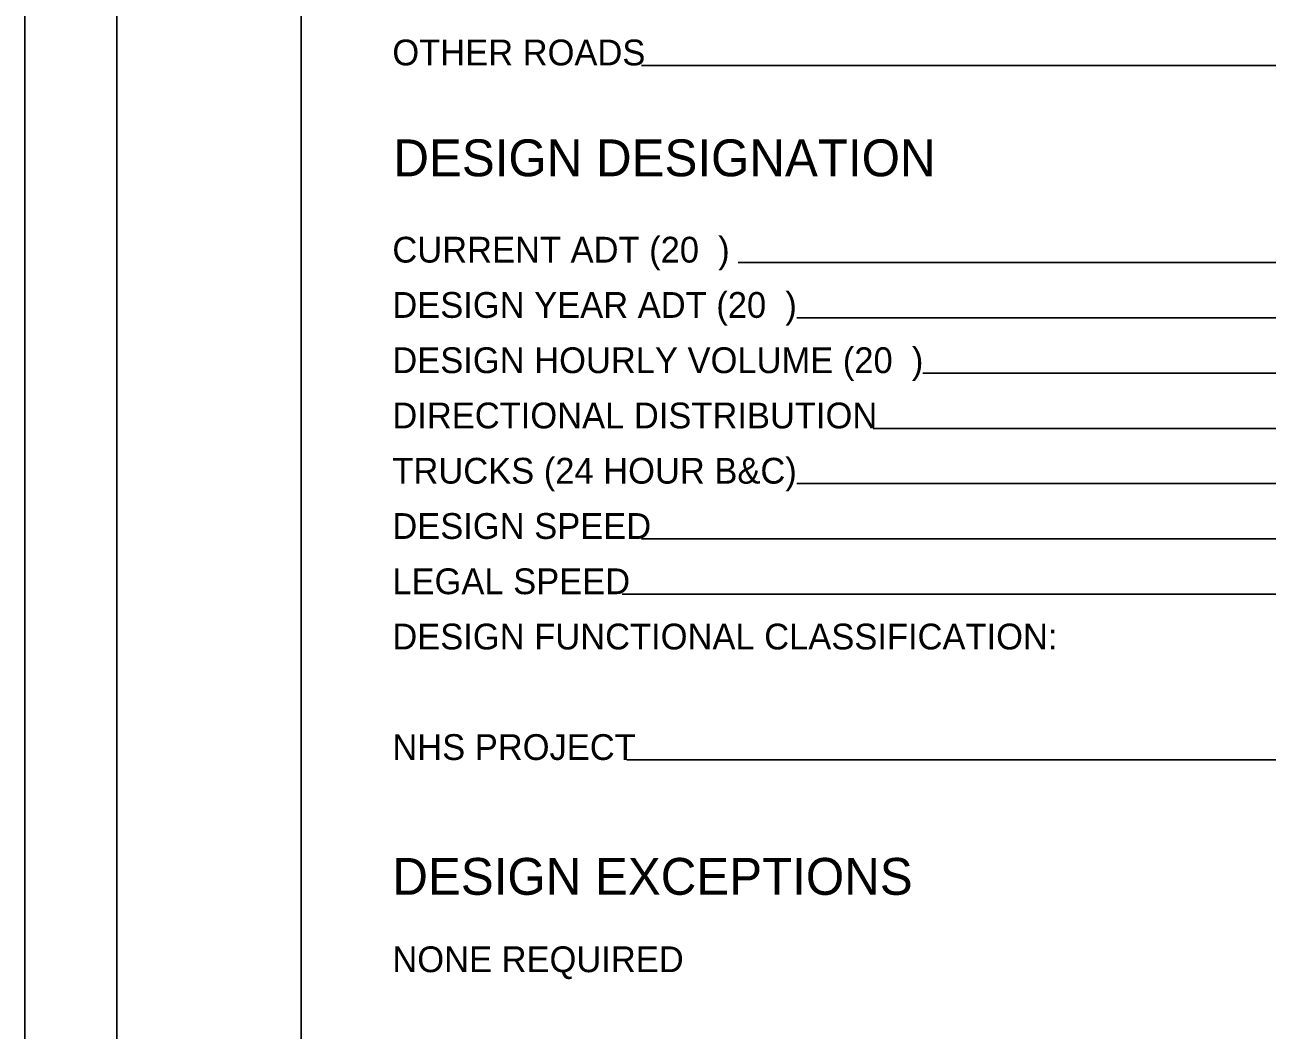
# Model space of a CAD drawing. Extents: x 0 to 34, y 0 to 22.
# Drawn here: x 0 to 6.74, y 5.64 to 11.1 of the extents above; entities that cross this region are included whole.
import ezdxf

# ---------------------------------------------------------------- set-up
doc = ezdxf.new("R2010")
doc.units = 0
for name, color, linetype in [('SH_Border', 7, 'Continuous'), ('SH_Cut_Line', 7, 'Continuous'), ('SH_Data', 7, 'Continuous'), ('SH_Text', 7, 'Continuous')]:
    doc.layers.add(name, color=color, linetype=linetype)

msp = doc.modelspace()

# ---------------------------------------------------------------- linework, layer by layer
at = {"layer": 'SH_Border'}
for points in [[(0.5, 21.5), (1.5, 21.5), (1.5, 0.5), (0.5, 0.5)], [(1.5, 21.5), (33.5, 21.5), (33.5, 0.5), (1.5, 0.5)]]:
    msp.add_lwpolyline(points, close=True, dxfattribs=at)
at = {"layer": 'SH_Cut_Line'}
msp.add_lwpolyline([(0, 0), (34, 0), (34, 22), (0, 22)], close=True, dxfattribs=at)
at = {"layer": 'SH_Data'}
for p, q in [((7.7, 10.8767), (3.3471, 10.8767)), ((7.6424, 9.8062), (3.871, 9.8062)), ((7.6368, 9.5062), (4.1885, 9.5062)), ((7.6368, 9.2062), (4.8723, 9.2062)), ((7.6368, 8.9062), (4.6037, 8.9062)), ((7.6368, 8.6062), (4.1885, 8.6062)), ((7.6368, 8.3062), (3.346, 8.3062)), ((7.6368, 8.0062), (3.2422, 8.0062)), ((7.6368, 7.1062), (3.2669, 7.1062))]:
    msp.add_line(p, q, dxfattribs=at)

# ---------------------------------------------------------------- texts
msp.add_text('DESIGN DESIGNATION', height=0.2, dxfattribs=at).set_placement((2, 10.2747))
at = {"layer": 'SH_Text'}
for s, height, p in [('OTHER ROADS', 0.14, (1.9944, 10.8767)), ('CURRENT ADT (20  )', 0.14, (1.9944, 9.8062)), ('DESIGN YEAR ADT (20  )', 0.14, (1.9944, 9.5062)), ('DESIGN HOURLY VOLUME (20  )', 0.14, (1.9944, 9.2062)), ('DIRECTIONAL DISTRIBUTION', 0.14, (1.9944, 8.9062)), ('TRUCKS (24 HOUR B&C)', 0.14, (1.9944, 8.6062)), ('DESIGN SPEED', 0.14, (1.9944, 8.3062)), ('LEGAL SPEED', 0.14, (1.9944, 8.0062)), ('DESIGN FUNCTIONAL CLASSIFICATION:', 0.14, (1.9944, 7.7062)), ('NHS PROJECT', 0.14, (1.9944, 7.1062)), ('DESIGN EXCEPTIONS', 0.2, (1.9944, 6.3744)), ('NONE REQUIRED', 0.14, (1.9944, 5.9544))]:
    msp.add_text(s, height=height, dxfattribs=at).set_placement(p)

doc.saveas('drawing.dxf')
